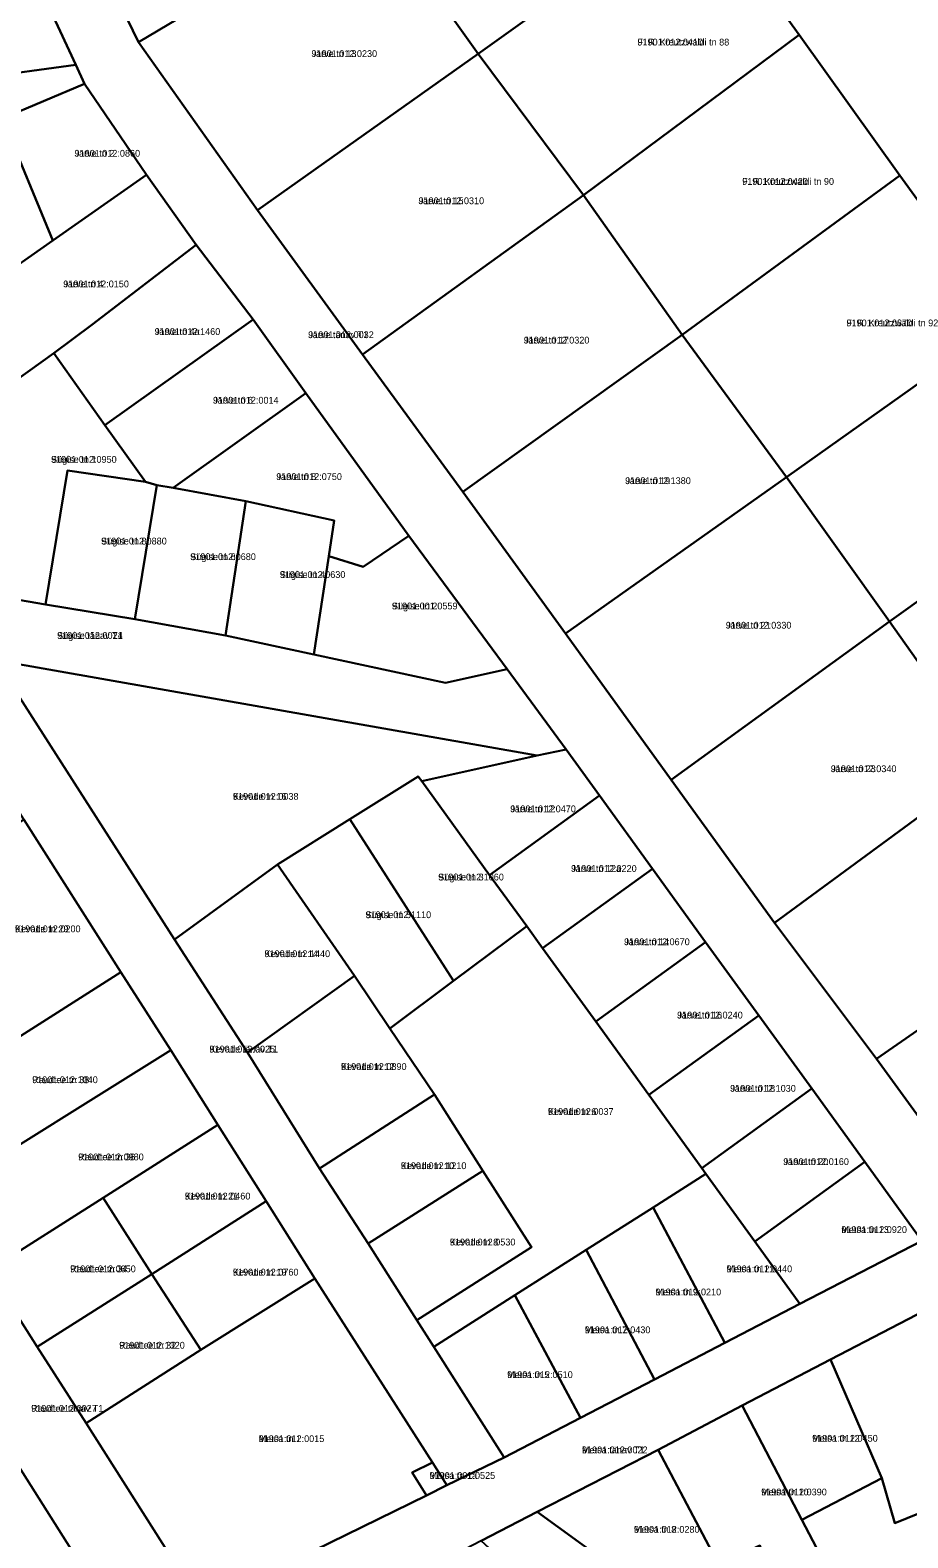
# Model space of a CAD drawing. Extents: x 675810 to 681273, y 6411190 to 6417565.
# Drawn here: x 678437.2 to 678631.2, y 6413720.5 to 6414053.8 of the extents above; entities that cross this region are included whole.
import ezdxf

# ---------------------------------------------------------------- set-up
doc = ezdxf.new("R2010")
doc.units = 0
for name, color, linetype in [('L_AADRESS', 7, 'Continuous'), ('PIIR', 7, 'Continuous'), ('TUNNUS', 7, 'Continuous')]:
    doc.layers.add(name, color=color, linetype=linetype)

msp = doc.modelspace()

# ---------------------------------------------------------------- linework, layer by layer
at = {"layer": 'PIIR'}
for points in [[(678556.46, 6414125.01), (678564.11, 6414112.81), (678512.57, 6414081.71), (678461.15, 6414051.17), (678455.05, 6414063.83), (678505.13, 6414093.59)], [(678512.57, 6414081.71), (678564.11, 6414112.81), (678585.04, 6414083.51), (678536.24, 6414048.53)], [(678536.24, 6414048.53), (678585.04, 6414083.51), (678607.22, 6414052.75), (678559.55, 6414017.28)], [(678461.15, 6414051.17), (678512.57, 6414081.71), (678536.24, 6414048.53), (678487.43, 6414014.01)], [(678559.55, 6414017.28), (678607.22, 6414052.75), (678629.43, 6414021.69), (678581.34, 6413986.43)], [(678404.04, 6414040.23), (678447.32, 6414046.14), (678449.23, 6414041.96), (678431.1, 6414034.24), (678416.31, 6414027.98)], [(678536.24, 6414048.53), (678559.55, 6414017.28), (678510.64, 6413982.1), (678487.43, 6414014.01)], [(678462.89, 6414021.78), (678442.2, 6414007.27), (678431.1, 6414034.24), (678449.23, 6414041.96)], [(678431.1, 6414034.24), (678442.2, 6414007.27), (678412.15, 6413986.24), (678407.31, 6413991.8), (678395.84, 6414019.23), (678410.26, 6414025.4), (678416.31, 6414027.98)], [(678473.89, 6414006.35), (678450.83, 6413988.67), (678442.46, 6413982.42), (678428.01, 6413972.09), (678412.15, 6413986.24), (678442.2, 6414007.27), (678462.89, 6414021.78)], [(678629.43, 6414021.69), (678652.89, 6413989.37), (678604.38, 6413954.95), (678581.34, 6413986.43)], [(678559.55, 6414017.28), (678581.34, 6413986.43), (678532.87, 6413951.73), (678510.64, 6413982.1)], [(678486.46, 6413989.85), (678453.73, 6413966.46), (678442.46, 6413982.42), (678450.83, 6413988.67), (678473.89, 6414006.35)], [(678486.46, 6413989.85), (678498.13, 6413973.57), (678468.79, 6413952.6), (678465.18, 6413953.23), (678462.72, 6413953.96), (678453.73, 6413966.46)], [(678652.89, 6413989.37), (678676.11, 6413958.07), (678627.16, 6413923.09), (678604.38, 6413954.95)], [(678532.87, 6413951.73), (678581.34, 6413986.43), (678604.38, 6413954.95), (678555.52, 6413920.44)], [(678428.01, 6413972.09), (678442.46, 6413982.41), (678453.73, 6413966.46), (678462.72, 6413953.96), (678445.45, 6413956.43), (678440.59, 6413926.81), (678420.93, 6413930.19), (678426, 6413960.19)], [(678520.91, 6413941.97), (678510.78, 6413935.13), (678503.2, 6413937.54), (678504.38, 6413945.41), (678484.86, 6413949.64), (678468.79, 6413952.6), (678498.13, 6413973.57)], [(678440.59, 6413926.81), (678445.45, 6413956.43), (678462.72, 6413953.96), (678465.18, 6413953.23), (678460.33, 6413923.61)], [(678676.11, 6413958.07), (678698.2, 6413927.02), (678678.94, 6413912.96), (678649.52, 6413891.54), (678627.16, 6413923.09)], [(678465.18, 6413953.23), (678468.79, 6413952.6), (678484.86, 6413949.64), (678480.38, 6413919.98), (678460.33, 6413923.61)], [(678604.38, 6413954.95), (678627.16, 6413923.09), (678578.93, 6413888.03), (678555.52, 6413920.44)], [(678484.86, 6413949.64), (678504.38, 6413945.41), (678503.2, 6413937.54), (678499.93, 6413915.74), (678480.38, 6413919.98)], [(678330.34, 6413945.03), (678341.89, 6413943.13), (678361.56, 6413940.14), (678381.59, 6413936.81), (678401.49, 6413933.61), (678420.93, 6413930.19), (678440.59, 6413926.81), (678460.33, 6413923.61), (678480.38, 6413919.98), (678499.93, 6413915.74), (678528.98, 6413909.5), (678542.68, 6413912.5), (678555.72, 6413894.78), (678549.27, 6413893.41), (678429.5, 6413914.49), (678411.69, 6413917.59), (678362.56, 6413926.23), (678331.41, 6413931.37)], [(678520.91, 6413941.97), (678542.68, 6413912.5), (678528.98, 6413909.5), (678499.93, 6413915.74), (678503.2, 6413937.54), (678510.78, 6413935.13)], [(678627.16, 6413923.09), (678649.52, 6413891.54), (678601.75, 6413856.43), (678578.93, 6413888.03)], [(678411.69, 6413917.59), (678429.5, 6413914.49), (678469.14, 6413852.8), (678485.25, 6413827.78), (678501.14, 6413802.16), (678511.94, 6413785.53), (678522.67, 6413768.65), (678526.43, 6413762.74), (678541.98, 6413738.26), (678529.34, 6413732.11), (678526.12, 6413737.17), (678500.14, 6413777.83), (678489.4, 6413794.9), (678478.68, 6413811.78), (678468.27, 6413828.33), (678457.22, 6413845.53), (678435.77, 6413879.29), (678425.05, 6413896.17), (678414.63, 6413912.8)], [(678429.5, 6413914.49), (678549.27, 6413893.41), (678523.76, 6413887.76), (678523, 6413888.82), (678507.85, 6413879.34), (678491.9, 6413869.36), (678469.14, 6413852.8)], [(678563.07, 6413884.61), (678538.76, 6413867.02), (678523.76, 6413887.76), (678549.27, 6413893.41), (678555.72, 6413894.78)], [(678649.52, 6413891.54), (678672.38, 6413860.64), (678648.07, 6413842.86), (678624.26, 6413826.39), (678601.75, 6413856.43)], [(678523, 6413888.82), (678523.76, 6413887.76), (678538.76, 6413867.02), (678546.96, 6413855.68), (678530.79, 6413843.66), (678507.85, 6413879.34)], [(678574.79, 6413868.4), (678550.49, 6413850.82), (678546.96, 6413855.68), (678538.76, 6413867.02), (678563.07, 6413884.61)], [(678431.9, 6413829.44), (678421.17, 6413846.32), (678415.64, 6413854.51), (678410.45, 6413863.2), (678435.77, 6413879.29), (678457.22, 6413845.53)], [(678530.79, 6413843.66), (678516.72, 6413833.1), (678508.87, 6413844.75), (678491.9, 6413869.36), (678507.85, 6413879.34)], [(678491.9, 6413869.36), (678508.87, 6413844.75), (678485.25, 6413827.78), (678469.14, 6413852.8)], [(678550.49, 6413850.82), (678574.79, 6413868.4), (678586.52, 6413852.2), (678562.21, 6413834.62)], [(678516.72, 6413833.1), (678530.79, 6413843.66), (678546.96, 6413855.68), (678550.49, 6413850.82), (678562.21, 6413834.62), (678573.94, 6413818.41), (678585.66, 6413802.21), (678586.59, 6413800.94), (678574.92, 6413793.55), (678560.1, 6413784.14), (678544.37, 6413774.15), (678526.43, 6413762.74), (678522.67, 6413768.65), (678548, 6413784.74), (678537.27, 6413801.62), (678526.58, 6413818.49)], [(678598.25, 6413836), (678573.94, 6413818.41), (678562.21, 6413834.62), (678586.52, 6413852.2)], [(678431.9, 6413829.44), (678457.22, 6413845.53), (678468.27, 6413828.33), (678417.3, 6413796.48), (678406.61, 6413813.23)], [(678508.87, 6413844.75), (678516.72, 6413833.1), (678526.58, 6413818.49), (678501.14, 6413802.16), (678485.25, 6413827.78)], [(678648.07, 6413842.86), (678671.57, 6413810.13), (678673.96, 6413806.78), (678648.24, 6413793.43), (678624.26, 6413826.39)], [(678609.97, 6413819.8), (678585.66, 6413802.21), (678573.94, 6413818.41), (678598.25, 6413836)], [(678417.3, 6413796.48), (678468.27, 6413828.33), (678478.68, 6413811.78), (678453.35, 6413795.69), (678428.02, 6413779.57)], [(678621.7, 6413803.59), (678597.39, 6413786.01), (678586.59, 6413800.94), (678585.66, 6413802.21), (678609.97, 6413819.8)], [(678501.14, 6413802.16), (678526.58, 6413818.49), (678537.27, 6413801.62), (678511.94, 6413785.53)], [(678489.4, 6413794.9), (678464.07, 6413778.81), (678453.35, 6413795.69), (678478.68, 6413811.78)], [(678597.39, 6413786.01), (678621.7, 6413803.59), (678634.29, 6413786.17), (678607.37, 6413772.19)], [(678511.94, 6413785.53), (678537.27, 6413801.62), (678548, 6413784.74), (678522.67, 6413768.65)], [(678607.37, 6413772.19), (678590.79, 6413763.59), (678574.92, 6413793.55), (678586.59, 6413800.94), (678597.39, 6413786.01)], [(678464.07, 6413778.81), (678438.75, 6413762.72), (678428.02, 6413779.57), (678453.35, 6413795.69)], [(678500.14, 6413777.83), (678474.92, 6413762.05), (678464.07, 6413778.81), (678489.4, 6413794.9)], [(678575.25, 6413755.53), (678560.1, 6413784.14), (678574.92, 6413793.55), (678590.79, 6413763.59)], [(678634.29, 6413786.17), (678640.77, 6413773.75), (678614.14, 6413759.93), (678594.62, 6413749.78), (678576.03, 6413739.92), (678549.31, 6413726.23), (678536.93, 6413719.83), (678510.3, 6413706), (678483.68, 6413692.21), (678475.14, 6413705.51), (678524.84, 6413729.88), (678529.34, 6413732.11), (678541.98, 6413738.26), (678558.84, 6413747.01), (678575.25, 6413755.53), (678590.79, 6413763.59), (678607.37, 6413772.19)], [(678544.37, 6413774.15), (678560.1, 6413784.14), (678575.25, 6413755.53), (678558.84, 6413747.01)], [(678438.75, 6413762.72), (678464.07, 6413778.81), (678474.92, 6413762.05), (678449.57, 6413745.82)], [(678500.14, 6413777.83), (678526.12, 6413737.17), (678521.64, 6413734.97), (678524.84, 6413729.88), (678475.14, 6413705.51), (678449.57, 6413745.82), (678474.92, 6413762.05)], [(678541.98, 6413738.26), (678526.43, 6413762.74), (678544.37, 6413774.15), (678558.84, 6413747.01)], [(678656.69, 6413735.21), (678628.37, 6413723.73), (678625.5, 6413733.71), (678614.14, 6413759.93), (678640.77, 6413773.75)], [(678594.62, 6413749.78), (678614.14, 6413759.93), (678625.5, 6413733.71), (678607.75, 6413724.49)], [(678589.34, 6413714.68), (678576.03, 6413739.92), (678594.62, 6413749.78), (678607.75, 6413724.49), (678621.57, 6413698.17), (678604.03, 6413703.32), (678598.52, 6413718.81)], [(678576.03, 6413739.92), (678589.34, 6413714.68), (678598.52, 6413718.81), (678604.03, 6413703.32), (678584.77, 6413709.31), (678563.8, 6413715.72), (678549.31, 6413726.23)], [(678434.67, 6413736.25), (678459.09, 6413697.62), (678408.15, 6413673.4), (678387.78, 6413706.37)], [(678529.34, 6413732.11), (678524.84, 6413729.88), (678521.64, 6413734.97), (678526.12, 6413737.17)], [(678636.17, 6413693.6), (678621.57, 6413698.17), (678607.75, 6413724.49), (678625.5, 6413733.71), (678628.37, 6413723.73), (678656.69, 6413735.21), (678665.33, 6413711.42)], [(678549.31, 6413726.23), (678563.8, 6413715.72), (678584.77, 6413709.31), (678583.58, 6413705.42), (678580.76, 6413696.15), (678561.63, 6413701.98), (678555.69, 6413705.21), (678548.71, 6413709), (678536.93, 6413719.83)]]:
    msp.add_lwpolyline(points, close=True, dxfattribs=at)
for points in [[(678844.5, 6413635.09), (678836.58, 6413654.64), (678829.99, 6413669.89), (678824.57, 6413684.49), (678818.45, 6413699.81), (678801.76, 6413744.69), (678786.44, 6413789.37), (678766.12, 6413838.87), (678744.62, 6413862.85), (678721.35, 6413895.39), (678713.07, 6413906.74), (678698.2, 6413927.02), (678676.11, 6413958.07), (678652.89, 6413989.37), (678629.43, 6414021.69), (678607.22, 6414052.75), (678585.04, 6414083.51)], [(678439.84, 6414062.16), (678447.32, 6414046.14), (678404.04, 6414040.23), (678416.31, 6414027.98), (678410.26, 6414025.4), (678400.35, 6414035.3), (678395.84, 6414019.23), (678389.31, 6414016.6), (678395.59, 6414039.05), (678370.36, 6414039.6), (678358.38, 6414003.67), (678352.46, 6414001.13), (678334.04, 6413993.38), (678306.95, 6413981.95), (678290.84, 6413991.05), (678344.97, 6414015.74), (678351.41, 6414021.65), (678357.53, 6414040.01), (678331.66, 6414042.24), (678306.31, 6414047.32), (678287.14, 6414052.45), (678242.2, 6414072.95)], [(678455.05, 6414063.83), (678461.15, 6414051.17), (678487.43, 6414014.01), (678510.64, 6413982.1), (678532.87, 6413951.73), (678555.52, 6413920.44), (678578.93, 6413888.03), (678601.75, 6413856.43), (678624.26, 6413826.39), (678648.24, 6413793.43)], [(678634.29, 6413786.17), (678621.7, 6413803.59), (678609.97, 6413819.8), (678598.25, 6413836), (678586.52, 6413852.2), (678574.79, 6413868.4), (678563.07, 6413884.61), (678555.72, 6413894.78), (678542.68, 6413912.5), (678520.91, 6413941.97), (678498.13, 6413973.57), (678486.46, 6413989.85), (678473.89, 6414006.35), (678462.89, 6414021.78), (678449.23, 6414041.96), (678447.32, 6414046.14), (678439.84, 6414062.16)], [(678428.02, 6413779.57), (678438.75, 6413762.72), (678449.57, 6413745.82), (678475.14, 6413705.51)], [(678459.09, 6413697.62), (678434.67, 6413736.25)]]:
    msp.add_lwpolyline(points, dxfattribs=at)

# ---------------------------------------------------------------- texts
at = {"layer": 'L_AADRESS'}
for s, p in [('Järve tn 13', (678499.39, 6414047.86)), ('F. R. Kreutzwaldi tn 88', (678571.45, 6414050.4)), ('Järve tn 2', (678447, 6414025.82)), ('F. R. Kreutzwaldi tn 90', (678594.61, 6414019.59)), ('Järve tn 15', (678523.05, 6414015.32)), ('Järve tn 4', (678444.52, 6413996.94)), ('F. R. Kreutzwaldi tn 92', (678617.66, 6413988.32)), ('Järve tn 4a', (678464.72, 6413986.41)), ('Järve tänav T1', (678498.66, 6413985.71)), ('Järve tn 17', (678546.32, 6413984.51)), ('Järve tn 6', (678477.62, 6413971.23)), ('Sügise tn 10', (678441.82, 6413958.15)), ('Järve tn 8', (678491.61, 6413954.35)), ('Järve tn 19', (678568.74, 6413953.44)), ('Sügise tn 8', (678452.89, 6413940.09)), ('Sügise tn 6', (678472.59, 6413936.64)), ('Sügise tn 4', (678492.38, 6413932.69)), ('Sügise tn 2', (678517.17, 6413925.74)), ('Järve tn 21', (678590.98, 6413921.49)), ('Sügise tänav T1', (678443.15, 6413919.22)), ('Järve tn 23', (678614.2, 6413889.76)), ('Kevade tn 16', (678482.02, 6413883.65)), ('Järve tn 12', (678543.33, 6413880.9)), ('Järve tn 12a', (678556.78, 6413867.71)), ('Sügise tn 3', (678527.41, 6413865.82)), ('Sügise tn 5', (678511.34, 6413857.49)), ('Kevade tn 29', (678433.84, 6413854.37)), ('Järve tn 14', (678568.5, 6413851.51)), ('Kevade tn 14', (678489, 6413848.87)), ('Järve tn 16', (678580.22, 6413835.3)), ('Kevade tänav T1', (678476.83, 6413827.78)), ('Raudtee tn 38', (678437.64, 6413821.01)), ('Kevade tn 12', (678505.91, 6413823.93)), ('Järve tn 18', (678591.95, 6413819.11)), ('Kevade tn 6', (678551.66, 6413813.99)), ('Raudtee tn 36', (678447.8, 6413803.95)), ('Kevade tn 10', (678519.13, 6413802.01)), ('Järve tn 20', (678603.69, 6413802.91)), ('Kevade tn 21', (678471.38, 6413795.29)), ('Metsa tn 13', (678616.52, 6413787.89)), ('Kevade tn 8', (678529.97, 6413785.13)), ('Raudtee tn 34', (678446.04, 6413779.21)), ('Kevade tn 19', (678482.01, 6413778.48)), ('Metsa tn 11', (678591.14, 6413779.21)), ('Metsa tn 9', (678575.45, 6413774.1)), ('Metsa tn 7', (678559.81, 6413765.73)), ('Raudtee tn 32', (678456.88, 6413762.32)), ('Metsa tn 5', (678542.64, 6413755.82)), ('Raudtee tänav T1', (678437.42, 6413748.36)), ('Metsa tn 1', (678487.72, 6413741.67)), ('Metsa tn 12', (678610.06, 6413741.75)), ('Metsa tänav T1', (678559.19, 6413739.19)), ('Metsa tn 1a', (678525.49, 6413733.53)), ('Metsa tn 10', (678598.8, 6413729.88)), ('Metsa tn 8', (678570.67, 6413721.62))]:
    msp.add_text(s, height=1.5, dxfattribs=at).set_placement(p)
at = {"layer": 'TUNNUS'}
for s, p in [('91901:012:0230', (678499.39, 6414047.86)), ('91901:012:0410', (678571.45, 6414050.4)), ('91901:012:0860', (678447, 6414025.82)), ('91901:012:0420', (678594.61, 6414019.59)), ('91901:012:0310', (678523.05, 6414015.32)), ('91901:012:0150', (678444.52, 6413996.94)), ('91901:012:0370', (678617.66, 6413988.32)), ('91901:012:1460', (678464.72, 6413986.41)), ('91901:012:0032', (678498.66, 6413985.71)), ('91901:012:0320', (678546.32, 6413984.51)), ('91901:012:0014', (678477.62, 6413971.23)), ('91901:012:0950', (678441.82, 6413958.15)), ('91901:012:0750', (678491.61, 6413954.35)), ('91901:012:1380', (678568.74, 6413953.44)), ('91901:012:0880', (678452.89, 6413940.09)), ('91901:012:0680', (678472.59, 6413936.64)), ('91901:012:0630', (678492.38, 6413932.69)), ('91901:001:0559', (678517.17, 6413925.74)), ('91901:012:0330', (678590.98, 6413921.49)), ('91901:012:0024', (678443.15, 6413919.22)), ('91901:012:0340', (678614.2, 6413889.76)), ('91901:012:0038', (678482.02, 6413883.65)), ('91901:012:0470', (678543.33, 6413880.9)), ('91901:012:0220', (678556.78, 6413867.71)), ('91901:012:1060', (678527.41, 6413865.82)), ('91901:012:1110', (678511.34, 6413857.49)), ('91901:012:0200', (678433.84, 6413854.37)), ('91901:012:0670', (678568.5, 6413851.51)), ('91901:012:1440', (678489, 6413848.87)), ('91901:012:0240', (678580.22, 6413835.3)), ('91901:012:0025', (678476.83, 6413827.78)), ('91901:012:1040', (678437.64, 6413821.01)), ('91901:012:0890', (678505.91, 6413823.93)), ('91901:012:1030', (678591.95, 6413819.11)), ('91901:012:0037', (678551.66, 6413813.99)), ('91901:012:0980', (678447.8, 6413803.95)), ('91901:012:1210', (678519.13, 6413802.01)), ('91901:012:0160', (678603.69, 6413802.91)), ('91901:012:0460', (678471.38, 6413795.29)), ('91901:012:0920', (678616.52, 6413787.89)), ('91901:012:0530', (678529.97, 6413785.13)), ('91901:012:0650', (678446.04, 6413779.21)), ('91901:012:0760', (678482.01, 6413778.48)), ('91901:012:0440', (678591.14, 6413779.21)), ('91901:012:0210', (678575.45, 6413774.1)), ('91901:012:0430', (678559.81, 6413765.73)), ('91901:012:1320', (678456.88, 6413762.32)), ('91901:012:0510', (678542.64, 6413755.82)), ('91901:012:0027', (678437.42, 6413748.36)), ('91901:012:0015', (678487.72, 6413741.67)), ('91901:012:0450', (678610.06, 6413741.75)), ('91901:012:0022', (678559.19, 6413739.19)), ('91901:001:0525', (678525.49, 6413733.53)), ('91901:012:0390', (678598.8, 6413729.88)), ('91901:012:0280', (678570.67, 6413721.62))]:
    msp.add_text(s, height=1.5, dxfattribs=at).set_placement(p)

doc.saveas('drawing.dxf')
